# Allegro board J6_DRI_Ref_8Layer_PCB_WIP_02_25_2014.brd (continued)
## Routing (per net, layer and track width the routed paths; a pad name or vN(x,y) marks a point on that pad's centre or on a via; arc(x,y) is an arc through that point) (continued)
H_DDR2_RASN: length 80.5
  TOP w0.102: v1(66.37,51.64) U52.T23
  TOP w0.127: U68.F3 79.83,26.98 79.96,27.1 80.11,27.1 80.57,27.56 TP2MA2.1 ; R286.1 v2(104.29,28.4) ; TP2MB2.1 94.92,27.56 94.46,27.1 94.31,27.1 94.18,26.98 U69.F3
  L3-SIGNAL w0.114: v2(65.68,36.78) 66.19,37.29 66.19,37.69 66.29,37.79 66.65,37.79 66.75,37.89 66.75,38.09 66.65,38.2 66.29,38.2 66.19,38.3 66.19,38.5 66.29,38.6 66.63,38.6 66.75,38.72 66.75,38.89 66.63,39.01 66.29,39.01 66.19,39.11 66.19,39.31 66.29,39.41 66.65,39.41 66.75,39.52 66.75,39.72 66.65,39.82 66.29,39.82 66.19,39.92 66.19,40.13 66.29,40.23 66.65,40.23 66.75,40.33 66.75,40.53 66.65,40.63 66.29,40.63 66.19,40.74 66.19,40.94 66.29,41.04 66.65,41.04 66.75,41.14 66.75,41.35 66.65,41.45 66.29,41.45 66.19,41.55 66.19,41.75 66.29,41.85 66.72,41.85 66.84,41.97 66.84,42.14 66.72,42.26 66.29,42.26 66.19,42.36 66.19,44.29 66.43,44.53 66.43,44.88 66.19,45.13 66.19,46.04 66.29,46.14 66.56,46.14 66.68,46.26 66.68,46.43 66.56,46.55 66.29,46.55 66.19,46.65 66.19,46.89 66.31,47.01 66.51,47.01 66.62,47.12 66.62,47.35 66.51,47.46 66.31,47.46 66.19,47.58 66.19,48.16 66.85,48.82 66.85,51.18 v1(66.37,51.64)
  L6-SIGNAL w0.102: v2(104.29,28.4) 103.43,28.4 103.28,28.55 102.52,28.55 102.3,28.33 102.3,27.96 102.03,27.69 100.91,27.69 100.46,27.23 99.85,27.23 99.59,27.49 97.38,27.49 96.77,28.09 96.29,28.09 TP2MB2.1 93.22,27.56 93.14,27.49 91.65,27.49 91.12,28.02 90.04,28.02 89.79,28.27 85.7,28.27 85.19,27.76 84.08,27.76 83.8,27.49 82.93,27.49 82.5,27.92 81.76,27.92 TP2MA2.1 79.17,27.56 78.99,27.38 78.26,27.38 78.13,27.51 77.5,27.51 75.08,29.92 75.08,30.56 71.78,33.86 70.51,33.86 68.35,36.02 68.35,36.16 68.74,36.55 68.74,36.72 68.62,36.84 68.45,36.84 68.06,36.45 67.92,36.45 67.59,36.78 v2(65.68,36.78)
  BOTTOM w0.127: TP2MB2.1 96.16,27.97 96.72,27.97 97.03,27.66 97.03,27.25 97.38,26.9 U115.F3 ; TP2MA2.1 81.81,27.97 82.37,27.97 82.68,27.66 82.68,27.25 83.03,26.9 U116.F3
H_DDR2_RST: length 74
  TOP w0.102: U52.R24 v1(66.36,50.84)
  TOP w0.127: U68.N2 79.03,20.49 79.4,20.12 v2(79.4,19.26) ; v2(93.75,19.26) 93.75,20.69 U69.N2
  L3-SIGNAL w0.102: v2(93.75,19.26) 92.22,19.26 91.87,18.91
  L3-SIGNAL w0.114: 91.87,18.91 81.38,18.91 80.64,19.64 79.79,19.64 v2(79.4,19.26) 79.07,18.93 72.87,18.93 v2(70.26,21.54)
  BOTTOM w0.102: v1(66.36,50.84) 66.36,50.31 66.56,50.11 66.56,49.04
  BOTTOM w0.127: v2(79.4,19.26) 79.79,18.86 82.69,18.86 83.31,19.48 83.31,20.54 U116.N2 ; U115.N2 97.66,20.54 97.66,19.48 97.04,18.86 94.15,18.86 v2(93.75,19.26) ; v2(70.26,21.54) 69.24,22.56 69.24,25 69.63,25.39 69.63,29.15 69.8,29.31 69.8,30.89 69.24,31.45 69.24,34.24 68.1,35.38 68.1,36.78 66.83,38.05 66.83,39.96 65.84,40.95 65.84,44.17 66.07,44.4 66.07,47.2 66.19,47.32 66.19,48.67 66.56,49.04
H_DDR2_WEN: length 77.9
  TOP w0.102: v1(65.63,49.82) U52.U25
  TOP w0.127: RN3.4 v1(104.3,25.93) ; U68.H3 80.28,25.06 80.61,25.39 81.33,25.39 TP2MA9.1 ; U69.H3 94.63,25.06 94.97,25.4 95.67,25.4 TP2MB9.1
  L3-SIGNAL w0.114: v2(65.18,35.13) 66.19,34.11 69.29,34.11 69.55,33.86 70.56,33.86 70.82,34.11 71.4,34.11 71.5,34.01 71.5,33.47 71.62,33.35 71.79,33.35 71.91,33.47 71.91,34.01 72.01,34.11 72.21,34.11 72.31,34.01 72.31,33.47 72.43,33.35 72.6,33.35 72.72,33.47 72.72,34.01 72.82,34.11 73.02,34.11 73.13,34.01 73.13,33.47 73.25,33.35 73.41,33.35 73.53,33.47 73.53,33.86 73.66,33.99 73.99,33.99 74.12,33.86 74.12,33 73.76,32.64 73.76,31.57 73.86,31.47 73.86,27.84 75.84,25.86 79.02,25.86 79.45,25.43 81.29,25.43 TP2MA9.1
  L6-SIGNAL w0.102: v1(104.3,25.93) 104.3,25.33 103.93,24.96 103.39,24.96 103.28,25.08 102.15,25.08 101.93,25.3 99.39,25.3 99.16,25.08 98.14,25.08 98.04,25.17 96.29,25.17 96.11,25.35 TP2MB9.1 94.89,25.35 94.59,25.05 94.39,25.05 94.26,25.17 94.26,25.35 94.13,25.48 93.57,25.48 93.45,25.35 93.45,25.17 93.32,25.05 92.71,25.05 92.38,25.38 84.89,25.38 84.58,25.07 83.87,25.07 83.74,25.2 83.74,25.35 83.62,25.48 83.26,25.48 82.96,25.17 81.89,25.17 TP2MA9.1
  BOTTOM w0.102: 65.31,48.88 65.21,48.99 65.21,49.49 65.36,49.64 v1(65.63,49.82) ; U116.H3 82.79,25.06 82.5,25.35 TP2MA9.1 ; U115.H3 97.14,25.06 96.85,25.35 TP2MB9.1
  BOTTOM w0.127: v2(65.18,35.13) 65.68,35.64 65.68,36.15 65.18,36.65 65.18,39.5 64.8,39.88 64.8,44.88 65.19,45.27 65.19,47.73 65.31,47.85 65.31,48.88
H_EMU0: length 0.5
  TOP w0.102: v1(72.75,53.27) U52.G21
H_EMU1: length 1.1
  TOP w0.102: U52.D24 75.53,50.4 v1(75.72,50.22)
H_GPIO5_18: length 10.1
  TOP w0.102: U52.V2 64.27,68.86 64,69.13 64,70.92
  TOP w0.127: 64.21,78.56 64.21,74.4 63.83,74.02 63.83,71.58 64,71.41 64,70.92
H_GPIO5_19: length 0.7
  TOP w0.102: v1(62.74,70.31) 62.73,70.3 U52.Y1
H_GPIO6_10: length 0.6
  TOP w0.102: U52.AC5 v1(59.94,66.86)
H_GPIO6_11: length 0.6
  TOP w0.102: 61.13,67.26 v1(60.73,67.64)
H_GPIO6_16: length 0.5
  TOP w0.102: v1(73.58,53.25) U52.F21
H_GPIO6_28: length 0.6
  TOP w0.102: U52.Y9 v1(62.33,63.68)
H_GPIO7_7: length 0.6
  TOP w0.102: U52.A25 v1(78.33,50.04)
H_GPIO7_8: length 0.6
  TOP w0.102: v1(74.33,58.05) U52.F16
H_GPIO7_9: length 0.6
  TOP w0.102: U52.B25 v1(77.53,50.04)
H_GPIO7_10: length 12.2
  TOP w0.102: 79.2,51.25 U52.A24
  TOP w0.127: 79.2,51.25 79.59,51.25 79.96,50.88 89.99,50.88
H_GPIO7_11: length 12.4
  TOP w0.102: U52.A22 78.11,52.68 79.04,52.68 79.2,52.53
  TOP w0.127: 79.2,52.53 80.34,51.39 89.74,51.39
H_GPMC_A1: length 0.6
  TOP w0.102: U52.T9 v1(65.53,63.7)
H_GPMC_A2: length 0.6
  TOP w0.102: v1(65.49,66.06) U52.T6
H_GPMC_A3: length 0.6
  TOP w0.102: v1(66.33,64.46) U52.T7
H_GPMC_A4: length 0.5
  TOP w0.102: U52.P6 v1(67.94,65.3)
H_GPMC_A5: length 0.6
  TOP w0.102: v1(67.13,63.65) U52.R9
H_GPMC_A6: length 0.6
  TOP w0.102: v1(66.34,66.01) U52.R5
H_GPMC_A7: length 0.6
  TOP w0.102: U52.P5 v1(67.98,66.86)
H_GPMC_A8: length 0.6
  TOP w0.102: v1(67.91,64.46) U52.N7
H_GPMC_A9: length 0.8
  TOP w0.102: U52.R4 v1(66.23,67.89)
H_GPMC_A10: length 0.5
  TOP w0.102: U52.N9 v1(67.97,63.65)
H_GPMC_A11: length 0.6
  TOP w0.102: v1(67.13,62.87) U52.P9
H_GPMC_A12: length 0.7
  TOP w0.102: U52.P4 67.67,67.4 v1(68.09,67.76)
H_GPMC_ADV_N: length 9.1
  TOP w0.102: 68.33,70.92 U52.N1
  TOP w0.127: 68.33,70.92 68.33,71.26 68.47,71.39 68.47,74.08 69.04,74.65 69.04,78.44
H_GPMC_BEN0: length 0.5
  TOP w0.102: U52.N6 67.99,66.04 67.98,66.05 v1(67.98,66.05)
H_GPMC_BEN1: length 0.8
  TOP w0.102: v1(68.63,67.89) U52.M4
H_GPMC_CLK: length 0.6
  TOP w0.102: U52.P7 v1(67.11,64.47)
H_GPMC_CS0_N: length 9.2
  TOP w0.102: 65.93,70.92 U52.T1
  TOP w0.127: 65.93,70.92 65.93,70.92 65.93,74.18 66.62,74.88 66.62,78.56
H_GPMC_CS1_N: length 0.5
  TOP w0.102: U52.H6 v1(72.74,65.3)
H_GPMC_CS2_N: length 10.3
  TOP w0.102: 67.13,70.92 67.13,69.42 67.53,69.02 U52.P2
  TOP w0.127: 67.13,70.92 67.13,71.46 67.7,72.03 67.7,73.92 67.13,74.49 67.13,78.51
H_GPMC_CS3_N: length 9.2
  TOP w0.102: 67.53,70.92 U52.P1
  TOP w0.127: 68.53,78.44 68.53,74.86 67.96,74.29 67.96,71.9 67.53,71.47 67.53,70.92
H_GPMC_D00: length 0.6
  TOP w0.102: U52.M6 v1(68.74,65.26)
H_GPMC_D01: length 9.9
  TOP w0.102: U52.M2 69.13,69.07 68.78,69.42 68.78,70.92
  TOP w0.127: 69.29,78.44 69.29,74.55 68.81,74.06 68.81,70.94 68.78,70.92
H_GPMC_D02: length 0.6
  TOP w0.102: v1(70.38,66.86) U52.L5
H_GPMC_D03: length 9.1
  TOP w0.102: U52.M1 69.13,70.92
  TOP w0.127: 69.13,70.92 69.13,71.3 69.74,71.9 69.74,74.31 69.55,74.5 69.55,78.44
H_GPMC_D04: length 0.5
  TOP w0.102: v1(70.34,65.3) U52.L6
H_GPMC_D05: length 0.7
  TOP w0.102: v1(70.49,67.76) U52.L4
H_GPMC_D06: length 0.7
  TOP w0.102: U52.L3 v1(70.52,68.37)
H_GPMC_D07: length 10.5
  TOP w0.102: 69.55,70.92 69.55,69.29 69.93,68.91 U52.L2
  TOP w0.127: 69.55,70.92 69.55,70.95 70.62,72.03 70.62,73.92 70.43,74.11 70.43,74.12 69.8,74.75 69.8,78.44
H_GPMC_D08: length 9.6
  TOP w0.102: U52.L1 69.93,70.92
  TOP w0.127: 69.93,70.92 69.93,70.98 70.88,71.93 70.88,74.06 70.05,74.88 70.05,78.56
H_GPMC_D09: length 10.4
  TOP w0.102: U52.K2 70.73,68.87 70.31,69.29 70.31,70.92
  TOP w0.127: 70.31,70.92 70.31,70.99 71.13,71.82 71.13,74.18 70.31,75.01 70.31,78.44
H_GPMC_D10: length 9.1
  TOP w0.102: 71.53,70.92 U52.J1
  TOP w0.127: 71.53,70.92 71.53,71.41 71.7,71.58 71.7,73.87 72.21,74.37 72.21,78.44
H_GPMC_D11: length 10
  TOP w0.102: U52.J2 71.53,68.96 71.2,69.29 71.2,70.92
  TOP w0.127: 71.96,78.44 71.96,74.5 71.45,73.99 71.45,71.71 71.2,71.45 71.2,70.92
H_GPMC_D12: length 9.5
  TOP w0.102: U52.H1 72.33,70.69 72.56,70.92
  TOP w0.127: 73.99,78.44 73.99,74.75 73.67,74.44 73.67,72.03 72.56,70.92
H_GPMC_D13: length 0.6
  TOP w0.102: v1(71.07,68.45) U52.J3
H_GPMC_D14: length 10.2
  TOP w0.102: U52.H2 72.33,68.92 71.96,69.29 71.96,70.92
  TOP w0.127: 71.96,70.92 71.96,70.97 72.77,71.78 72.77,74.07 72.47,74.37 72.47,78.44
H_GPMC_D15: length 0.7
  TOP w0.102: v1(72.92,68.37) U52.H3
H_GPMC_OE_N: length 0.6
  TOP w0.102: v1(68.71,66.03) U52.M5
H_GPMC_WAIT0: length 10.1
  TOP w0.102: 67.89,70.92 67.89,69.29 68.33,68.86 U52.N2
  TOP w0.127: 67.89,70.92 67.89,71.33 68.21,71.64 68.21,74.19 68.78,74.76 68.78,78.44
H_GPMC_WE_N: length 0.6
  TOP w0.102: v1(68.67,68.45) U52.M3
H_HDMI_TX0+: length 7.9
  TOP w0.089: 48.58,56.5 54.5,56.5 54.91,56.92 56.26,56.92 U52.AH17
H_HDMI_TX0-: length 8.9
  TOP w0.089: U52.AG17 56.79,56.85 56.45,57.19 54.8,57.19 54.38,56.77 48.58,56.77
H_HDMI_TX1+: length 8.1
  TOP w0.089: 48.42,55.74 54.77,55.74 55.16,56.12 56.26,56.12 U52.AH18
H_HDMI_TX1-: length 8.9
  TOP w0.089: U52.AG18 56.79,56.39 55.05,56.39 54.66,56.01 48.53,56.01
H_HDMI_TX2+: length 8.4
  TOP w0.089: 48.1,55.06 55.41,55.06 55.67,55.32 56.26,55.32 U52.AH19
H_HDMI_TX2-: length 9
  TOP w0.089: U52.AG19 56.79,55.59 55.56,55.59 55.3,55.32 48.37,55.32
H_HDMI_TXC+: length 7.9
  TOP w0.089: 48.67,57.32 54.17,57.32 54.57,57.72 56.26,57.72 U52.AH16
H_HDMI_TXC-: length 8.7
  TOP w0.089: U52.AG16 56.79,57.99 54.46,57.99 54.05,57.58 48.78,57.58
H_I2C1_SCL: length 1.3
  TOP w0.102: U52.C21 v1(76.65,53.07) ; v1(76.73,54.9) U52.C20
H_I2C2_SCL: length 1.2
  TOP w0.102: v1(76.76,50.02) U52.C25 ; U52.F17 v1(73.54,57.25)
H_I2C3_SCL: length 0.5
  TOP w0.102: U52.F20 v1(73.54,54.82)
H_I2C3_SDA: length 0.6
  TOP w0.102: v1(75.14,53.2) U52.E21
H_JTAG_RTCK: length 0.6
  TOP w0.102: v1(75.2,55.67) 75.16,55.71 75.03,55.72 U52.E18
H_JTAG_TCK: length 0.5
  TOP w0.102: v1(74.35,54.79) U52.E20
H_JTAG_TDI: length 0.8
  TOP w0.102: U52.D23 v1(76.16,52.55)
H_JTAG_TDO: length 0.6
  TOP w0.102: U52.F19 74.29,55.55 v1(74.36,55.63)
H_JTAG_TMS: length 0.6
  TOP w0.102: v1(74.35,56.44) U52.F18
H_JTAG_TRST_N: length 0.8
  TOP w0.102: v1(76.16,54.95) U52.D20
H_LJCB_CLKN: length 11.7
  TOP w0.102: U52.AH15 53.8,58.45
  TOP w0.127: 45.06,59.31 45.95,59.31 46.38,58.88 51.97,58.88 52.4,58.45 53.09,58.45 53.21,58.33 53.58,58.33 53.69,58.45 53.8,58.45
H_MCASP1_ACLKR: length 18.4
  TOP w0.102: 79.2,59.77 78.56,59.77 78.49,59.69 77.6,59.69 77.16,59.26 U52.B14
  TOP w0.127: 95,59.96 86.62,59.96 86.11,59.45 82.52,59.45 82.21,59.77 79.2,59.77
H_MCASP1_ACLKX: length 0.6
  TOP w0.102: v1(76.73,59.72) U52.C14
H_MCASP1_AXR0: length 0.6
  TOP w0.102: v1(72.73,60.48) U52.G12
H_MCASP1_AXR1: length 0.5
  TOP w0.102: v1(73.58,60.45) U52.F12
H_MCASP1_AXR2: length 0.6
  TOP w0.102: v1(72.73,59.66) U52.G13
H_MCASP1_AXR3: length 0.6
  TOP w0.102: U52.J11 v1(71.93,62.06)
H_MCASP1_AXR4: length 0.6
  TOP w0.102: v1(75.13,60.4) 75.13,60.41 U52.E12
H_MCASP1_AXR5: length 0.6
  TOP w0.102: v1(74.33,60.5) U52.F13
H_MCASP1_AXR6: length 0.7
  TOP w0.102: U52.C12 v1(76.65,60.27)
H_MCASP1_AXR7: length 0.7
  TOP w0.102: U52.D12 v1(76.04,60.3)
H_MCASP1_AXR8: length 19.2
  TOP w0.102: U52.B12 77.13,61.01 77.42,61.29 79.2,61.29
  TOP w0.127: 79.2,61.29 79.6,61.29 80.21,60.68 81.94,60.68 82.23,60.98 84.29,60.98 85.06,60.21 85.79,60.21 87.05,61.47 94.87,61.47
H_MCASP1_AXR9: length 16.4
  TOP w0.102: 79.2,61.66 U52.A11
  TOP w0.127: 93.76,61.74 86.75,61.74 86.25,61.23 82.05,61.23 81.84,61.01 80.37,61.01 79.72,61.66 79.2,61.66
H_MCASP1_AXR10: length 18.9
  TOP w0.102: U52.B13 77.13,60.12 77.42,60.4 79.2,60.4
  TOP w0.127: 79.2,60.4 82.05,60.4 82.37,60.72 84.19,60.72 84.95,59.96 85.9,59.96 87.16,61.22 94.92,61.22
H_MCASP1_AXR11: length 0.7
  TOP w0.102: U52.A12 v1(78.61,60.78)
H_MCASP1_AXR12: length 0.6
  TOP w0.102: v1(74.29,59.65) U52.E14
H_MCASP1_AXR13: length 17.5
  TOP w0.102: 79.2,60.06 U52.A13
  TOP w0.127: 95.11,60.21 86.51,60.21 86.01,59.71 82.65,59.71 82.3,60.06 79.2,60.06
H_MCASP1_AXR14: length 0.6
  TOP w0.102: U52.G14 v1(73.54,59.65)
H_MCASP1_AXR15: length 21.7
  TOP w0.102: 79.2,58.75 78.47,58.75 78.38,58.84 74.29,58.84 73.93,59.19 U52.F14
  TOP w0.127: 79.2,58.75 79.4,58.75 80.04,59.39 82.16,59.39 82.35,59.2 86.22,59.2 86.72,59.71 94.82,59.71
H_MCASP1_FSR: length 0.5
  TOP w0.102: U52.J14 v1(71.89,59.65)
H_MCASP1_FSX: length 0.8
  TOP w0.102: U52.D14 v1(76.16,59.76)
H_MCASP2_ACLKR: length 0.6
  TOP w0.102: v1(75.14,58) U52.E15
H_MCASP2_ACLKX: length 0.6
  TOP w0.102: v1(78.32,55.65) U52.A19
H_MCASP2_AXR0: length 18.5
  TOP w0.102: 79.2,58.12 77.47,58.12 U52.B15
  TOP w0.127: 79.2,58.12 79.55,58.12 80.31,58.88 81.84,58.88 82.04,58.68 82.04,58.14 82.58,57.61 94.39,57.61
H_MCASP2_AXR1: length 17.6
  TOP w0.102: 79.2,58.45 U52.A15
  TOP w0.127: 79.2,58.45 79.48,58.45 80.16,59.13 81.98,59.13 82.17,58.94 83.27,58.94 84.35,57.86 94.74,57.86
H_MCASP2_AXR2: length 0.7
  TOP w0.102: U52.C15 v1(76.65,57.87)
H_MCASP2_AXR3: length 17.4
  TOP w0.102: 79.2,57.23 78.77,57.65 U52.A16
  TOP w0.127: 94.59,55.93 84.35,55.93 83.92,56.37 80.06,56.37 79.2,57.23
H_MCASP2_AXR4: length 0.7
  TOP w0.102: v1(76.04,57.9) U52.D15
H_MCASP2_AXR5: length 0.6
  TOP w0.102: v1(77.52,57.25) U52.B16
H_MCASP2_AXR6: length 0.5
  TOP w0.102: U52.B17 v1(77.52,56.47)
H_MCASP2_AXR7: length 0.6
  TOP w0.102: v1(78.32,57.25) U52.A17
H_MCASP2_FSR: length 11.8
  TOP w0.102: 79.2,55.45 78.93,55.45 U52.A20
  TOP w0.127: 89.36,55.45 79.2,55.45
H_MCASP2_FSX: length 0.6
  TOP w0.102: v1(78.32,56.45) U52.A18
H_MCASP3_ACLKX: length 0.6
  TOP w0.102: U52.B18 v1(77.53,55.65)
H_MCASP3_AFSX: length 0.5
  TOP w0.102: v1(73.58,58.05) U52.F15
H_MCASP3_AXR0: length 0.5
  TOP w0.102: U52.B19 v1(77.52,54.87)
H_MCASP3_AXR1: length 0.6
  TOP w0.102: v1(76.73,57.31) U52.C17
H_MCASP4_ACLKX: length 0.7
  TOP w0.102: U52.C18 v1(76.65,55.47)
H_MCASP4_AFSX: length 12.1
  TOP w0.102: 79.2,54.66 78.19,53.65 U52.A21
  TOP w0.127: 89.48,54.94 79.48,54.94 79.2,54.66
H_MCASP4_AXR0: length 0.5
  TOP w0.102: v1(72.75,58.04) U52.G16
H_MCASP4_AXR1: length 0.8
  TOP w0.102: v1(76.16,57.35) U52.D17
H_MCASP5_ACLKX: length 0.5
  TOP w0.102: v1(61.58,68.45) U52.AA3
H_MCASP5_AFSX: length 0.6
  TOP w0.102: 61.13,63.26 v1(61.53,62.87)
H_MCASP5_AXR0: length 0.6
  TOP w0.102: v1(61.49,67.64) 61.13,68.06
H_MCASP5_AXR1: length 0.6
  TOP w0.102: v1(61.51,66.89) U52.AA4
H_MDIO_D: length 0.7
  TOP w0.102: v1(65.68,67.76) U52.U4
H_MDIO_MCLK: length 9.2
  TOP w0.102: 64.33,70.92 U52.V1
  TOP w0.127: 64.33,70.92 64.33,71.32 64.78,71.77 64.78,74.06 64.47,74.37 64.47,78.56
H_MLBP_CLK_N: length 12.8
  TOP w0.089: 61.13,68.86 60.76,69.22 60.76,69.75 60.77,69.75 60.77,71.6 59.64,72.73 59.64,75.51 59.66,75.53 59.61,75.58 59.61,76.22 59.99,76.59 60.13,76.59 60.13,80.72
H_MLBP_CLK_P: length 12.1
  TOP w0.089: 60.4,80.72 60.4,76.32 60.1,76.32 59.85,76.07 59.85,75.72 60.04,75.53 59.91,75.4 59.91,72.84 61.04,71.71 61.04,69.75 61.13,69.66
H_MLBP_DAT_N: length 11.9
  TOP w0.089: U52.AA2 61.56,69.22 61.56,69.74 61.57,69.75 61.57,71.02 62.17,71.61 62.17,80.39
H_MLBP_DAT_P: length 11
  TOP w0.089: 62.43,80.39 62.43,71.5 61.84,70.91 61.84,69.75 U52.AA1
H_MLBP_SIG_N: length 14.7
  TOP w0.089: U52.AC2 59.9,69.28 59.9,71.34 58.86,72.38 58.86,75.95 58.86,75.95 58.86,76.3 58.5,76.66 58.5,78.14 59.35,78.99 59.35,81.52 58.71,82.16
H_MLBP_SIG_P: length 13.7
  TOP w0.089: U52.AC1 60.17,69.82 60.17,71.45 59.13,72.49 59.13,76.06 59.29,76.22 59.29,76.31 59.62,76.64 59.62,81.63 58.9,82.35
H_MMC1_CLK: length 0.6
  TOP w0.102: v1(63.12,66.06) U52.W6
H_MMC1_CMD: length 0.6
  TOP w0.102: v1(63.14,65.26) U52.Y6
H_MMC1_DAT0: length 0.5
  TOP w0.102: U52.AA6 v1(62.32,66.03)
H_MMC1_DAT1: length 0.7
  TOP w0.102: v1(63.28,67.76) U52.Y4
H_MMC1_DAT2: length 0.6
  TOP w0.102: v1(61.49,66.07) U52.AA5
H_MMC1_DAT3: length 0.7
  TOP w0.102: U52.Y3 v1(63.31,68.37)
H_MMC1_SD_CD: length 0.6
  TOP w0.102: v1(63.14,64.46) U52.W7
H_MMC2_CLK: length 0.5
  TOP w0.102: U52.J7 v1(71.16,64.46)
H_MMC2_DAT0: length 0.8
  TOP w0.102: v1(71.03,67.89) U52.J4
H_MMC2_DAT1: length 0.6
  TOP w0.102: U52.J6 v1(71.14,65.26)
H_MMC2_DAT2: length 0.7
  TOP w0.102: v1(72.89,67.76) U52.H4
H_MMC2_DAT3: length 0.6
  TOP w0.102: v1(72.78,66.86) U52.H5
H_MMC2_DAT4: length 0.6
  TOP w0.102: v1(70.35,64.46) U52.K7
H_MMC2_DAT5: length 0.6
  TOP w0.102: U52.M7 v1(68.73,64.46)
H_MMC2_DAT6: length 0.6
  TOP w0.102: v1(71.14,66.06) 71.14,66.01 U52.J5
H_MMC2_DAT7: length 0.5
  TOP w0.102: U52.K6 70.43,66.01 v1(70.38,66.06)
H_MMC3_CLK: length 0.5
  TOP w0.102: U52.AD4 v1(59.18,67.66)
H_MMC3_CMD: length 0.5
  TOP w0.102: U52.AC4 v1(59.95,67.64)
H_MMC3_DAT0: length 0.6
  TOP w0.102: v1(59.93,64.42) U52.AC7
H_MMC3_DAT1: length 0.6
  TOP w0.102: U52.AC6 v1(60.72,65.26)
H_MMC3_DAT2: length 0.6
  TOP w0.102: U52.AC9 v1(60.73,62.86)
H_MMC3_DAT3: length 0.5
  TOP w0.102: v1(59.93,68.42) 60.28,68.11 U52.AC3
H_MMC3_DAT4: length 0.6
  TOP w0.102: v1(60.71,64.46) U52.AC8
H_MMC3_DAT5: length 0.6
  TOP w0.102: v1(59.92,65.26) U52.AD6
H_MMC3_DAT6: length 0.6
  TOP w0.102: 61.13,64.06 v1(61.53,64.47)
H_MMC3_DAT7: length 0.6
  TOP w0.102: v1(60.71,66.85) 61.13,66.46
H_MMC4_CLK: length 0.5
  TOP w0.102: v1(75.09,50.05) U52.E25
H_MMC4_CMD: length 0.6
  TOP w0.102: U52.C27 v1(76.73,48.44)
H_MMC4_DAT0: length 4.6
  TOP w0.127: 75.53,48.05 76.34,47.25 76.94,47.25 77.24,47.55 78.82,47.55 v2(79.4,48.14)
H_MMC4_DAT1: length 0.6
  TOP w0.102: v1(75.92,49.25) U52.D26
H_MMC4_DAT2: length 0.6
  TOP w0.102: U52.D27 v1(75.93,48.44)
H_MMC4_DAT3: length 0.6
  TOP w0.102: 76.33,48.05 v1(76.73,47.64)
H_NMIN: length 0.7
  TOP w0.102: U52.D21 v1(76.04,53.1)
H_ON_OFF: length 0.5
  TOP w0.102: v1(62.34,61.27) U52.Y11
H_OSC0_RTN: length 0.7
  TOP w0.102: v1(57.71,57.74) U52.AF15
H_OSC0_XIN: length 6.5
  TOP w0.089: C128.1 40.53,56.15 40.53,56.88 40.87,57.22 42.41,57.22 42.49,57.13 Y6.1 ; v1(58.29,58.02) U52.AE15
H_OSC0_XOUT: length 6.4
  TOP w0.089: C126.1 40.87,58.22 40.87,57.58 40.96,57.49 42.41,57.49 42.49,57.58 Y6.2 ; v1(59.14,58.03) U52.AD15
H_OSC1_RTN: length 0.5
  TOP w0.089: U52.AC14 v1(60.68,59.66)
H_OSC1_XIN: length 0.6
  TOP w0.102: v1(59.94,58.04) U52.AC15
H_OSC1_XOUT: length 0.6
  TOP w0.089: U52.AC13 v1(59.94,59.66)
H_OSCRTC_XIN: length 0.7
  TOP w0.089: U52.AE14 v1(58.23,59.81)
H_OSCRTC_XOUT: length 0.6
  TOP w0.089: v1(59.13,59.66) U52.AD14
H_PCIE_RXN0: length 1.5
  TOP w0.102: U52.AG13 57.13,60.07 56.74,60.45 56.24,60.45 56.21,60.48 v1(55.83,60.48)
H_PCIE_RXN1: length 12.5
  TOP w0.102: 53.8,63.71 53.91,63.71 54.5,63.12 54.5,62.38 54.83,62.05 56.72,62.05 57.12,61.66 U52.AG11
  TOP w0.127: 45.87,63.71 53.8,63.71
H_PCIE_RXP0: length 11.6
  TOP w0.102: 53.8,60.91 54.13,60.58 54.13,60.43 54.5,60.06 U52.AH13
  TOP w0.127: 53.8,60.91 53.62,61.09 45.24,61.09
H_PCIE_RXP1: length 11.9
  TOP w0.102: U52.AH11 54.86,61.66 54.29,62.22 54.29,63.04 53.88,63.45 53.8,63.45
  TOP w0.127: 45.67,63.45 53.8,63.45
H_PCIE_TXN0: length 12.6
  TOP w0.102: U52.AG14 56.98,59.26 56.59,59.64 54.48,59.64 54.23,59.9 53.8,59.9
  TOP w0.127: 45.24,60.84 51.55,60.84 52.02,60.36 52.02,60.23 52.35,59.9 53.8,59.9
H_PCIE_TXN1: length 2.3
  TOP w0.102: U52.AG12 57.13,60.88 56.72,61.29 55.04,61.29
H_PCIE_TXP0: length 11.9
  TOP w0.102: U52.AH14 54.39,59.26 54.05,59.59 53.8,59.59
  TOP w0.127: 45.11,60.58 51.31,60.58 51.74,60.15 51.74,59.84 51.99,59.59 53.8,59.59
H_PCIE_TXP1: length 0.3
  TOP w0.102: U52.AH12 55.99,60.86
H_POR_N: length 0.5
  TOP w0.178: v1(74.32,53.22) U52.F22
H_QSPI1_D0: length 9.2
  TOP w0.102: 65.13,70.92 U52.U1
  TOP w0.127: 65.13,70.92 65.13,71.23 65.35,71.45 65.35,74.25 64.97,74.63 64.97,78.56
H_QSPI1_D1: length 0.7
  TOP w0.102: v1(68.12,68.37) U52.P3
H_QSPI1_D2: length 10.2
  TOP w0.102: U52.U2 65.13,68.88 64.72,69.29 64.72,70.92
  TOP w0.127: 64.72,78.56 64.72,74.5 65.1,74.12 65.1,71.58 64.72,71.2 64.72,70.92
H_QSPI1_D3: length 10.1
  TOP w0.102: 65.48,70.92 65.48,69.29 65.92,68.86 U52.T2
  TOP w0.127: 65.23,78.56 65.23,74.75 65.61,74.37 65.61,71.33 65.48,71.2 65.48,70.92
H_QSPI1_RTCLK: length 0.6
  TOP w0.102: v1(66.27,68.45) U52.R3
H_QSPI1_SCLK: length 10.1
  TOP w0.102: U52.R2 66.73,68.93 66.35,69.31 66.35,70.92
  TOP w0.127: 66.88,78.56 66.88,74.63 66.83,74.58 66.83,71.78 66.35,71.31 66.35,70.92
H_RESET_N: length 0.6
  TOP w0.178: v1(74.33,52.45) U52.E23
H_RGMII0_RXC: length 0.6
  TOP w0.102: v1(65.58,66.86) U52.U5
H_RGMII0_RXCTL: length 0.6
  TOP w0.102: U52.V5 v1(63.94,66.01)
H_RGMII0_RXD0: length 10.1
  TOP w0.102: U52.W2 63.53,68.96 63.2,69.29 63.2,70.92
  TOP w0.127: 63.2,70.92 63.2,71.5 63.58,71.88 63.58,73.54 62.81,74.3 62.81,78.34
H_RGMII0_RXD1: length 0.6
  TOP w0.102: U52.Y2 62.73,68.87 v1(62.33,69.27)
H_RGMII0_RXD2: length 0.6
  TOP w0.102: v1(63.87,68.45) U52.V3
H_RGMII0_RXD3: length 0.8
  TOP w0.102: U52.V4 v1(63.83,67.89)
H_RGMII0_TD0: length 0.5
  TOP w0.102: U52.U6 v1(65.54,65.3)
H_RGMII0_TD1: length 0.6
  TOP w0.102: U52.V6 v1(63.94,65.26)
H_RGMII0_TD2: length 0.6
  TOP w0.102: v1(65.51,64.46) U52.U7
H_RGMII0_TD3: length 0.6
  TOP w0.102: U52.V7 v1(63.93,64.46)
H_RGMII0_TXC: length 0.6
  TOP w0.102: v1(63.17,62.84) U52.W9
H_RGMII0_TXCTL: length 0.6
  TOP w0.102: v1(63.93,63.68) U52.V9
H_RMII_50MHZ_CLK: length 0.7
  TOP w0.102: v1(65.71,68.37) U52.U3
H_RSTOUT_N: length 0.5
  TOP w0.102: v1(73.55,52.41) 73.57,52.41 U52.F23
H_RSV_Y5: length 0.6
  TOP w0.102: v1(63.15,66.86) U52.Y5
H_SATA1_TXN0: length 39.1
  TOP w0.102: 53.8,66.12 53.92,66.12 54.52,65.52 54.52,64.35 55.26,63.6 56.82,63.6 57.13,63.29 U52.AG9 ; U52.AG15 57.09,58.45 56.69,58.85 54.31,58.85 53.98,59.18 53.8,59.18 ; U52.AG10 57.13,62.53 56.85,62.82 55.42,62.82 54.11,64.12 54.11,65.35 53.85,65.61 53.8,65.61
  TOP w0.127: 45.14,59.62 45.19,59.67 46.48,59.67 46.96,59.18 53.17,59.18 53.21,59.22 53.58,59.22 53.61,59.18 53.8,59.18 ; 53.8,66.12 52.15,66.12 50.88,64.85 46.48,64.85 ; 46.2,64.34 51.09,64.34 52.36,65.61 53.8,65.61
H_SATA1_TXP0: length 23.1
  TOP w0.102: U52.AH9 55.27,63.26 54.32,64.21 54.32,65.43 53.89,65.86 53.8,65.86 ; 53.8,63.96 53.94,63.96 55.45,62.46 U52.AH10
  TOP w0.127: 53.8,65.86 52.26,65.86 50.99,64.59 46.58,64.59 ; 45.95,63.96 53.8,63.96
H_UART1_DBG_RX1: length 0.6
  TOP w0.102: U52.B27 v1(77.53,48.44)
H_UART1_DBG_TX1: length 0.6
  TOP w0.102: v1(76.73,49.25) U52.C26
H_UART3_CTS: length 0.5
  TOP w0.102: U52.G17 72.76,57.23 v1(72.75,57.23)
H_UART3_RTS: length 13.1
  TOP w0.102: 79.2,50.88 77.55,50.88 77.17,51.25 U52.B24
  TOP w0.127: 79.2,50.88 79.58,50.88 79.83,50.62 89.99,50.62
H_UART3_RXD: length 2.8
  TOP w0.102: 79.2,49.65 U52.A26
  TOP w0.127: 80.74,49.65 79.2,49.65
H_UART3_TXD: length 13.4
  TOP w0.102: 79.2,52.15 78.94,52.4 77.6,52.4 77.15,52.85 U52.B22
  TOP w0.127: 89.87,51.13 80.21,51.13 79.2,52.15
H_UART4_LIN_RXD: length 12.9
  TOP w0.102: 79.2,54.28 78.21,53.3 77.49,53.3 U52.B21
  TOP w0.127: 89.36,54.69 79.6,54.69 79.2,54.28
H_UART4_LIN_TXD: length 12.8
  TOP w0.102: U52.B20 77.15,54.45 77.48,54.12 78.11,54.12 79.18,55.2 79.2,55.2
  TOP w0.127: 89.36,55.2 79.2,55.2
H_USB1_DM: length 0.5
  TOP w0.102: U52.AC12 v1(60.68,60.45)
H_USB1_DP: length 0.6
  TOP w0.102: U52.AD12 v1(59.95,60.46)
H_USB1_DRV_VBUS: length 0.6
  TOP w0.178: 61.13,62.46 v1(60.68,62.06)
H_USB2_DM: length 0.7
  TOP w0.102: U52.AF11 v1(57.61,62.26)
H_USB2_DP: length 0.7
  TOP w0.102: U52.AE11 58.59,61.8 v1(58.23,62.21)
H_USB2_DRV_VBUS: length 0.6
  TOP w0.178: U52.AC10 v1(59.92,62.06)
H_VIN1A_CLK0: length 2.2
  TOP w0.102: U52.AG8 57.1,64.06 56.72,64.44 v2(55.12,64.44)
H_VIN1A_D0: length 0.7
  TOP w0.102: v1(58.23,64.61) U52.AE8
H_VIN1A_D1: length 0.6
  TOP w0.102: v1(59.13,64.51) U52.AD8
H_VIN1A_D2: length 0.6
  TOP w0.102: U52.AG7 57.13,64.87 v1(56.74,65.26)
H_VIN1A_D3: length 0.6
  TOP w0.102: U52.AH6 v1(55.78,65.66)
H_VIN1A_D4: length 11.9
  TOP w0.102: 53.8,70.49 54.23,70.49 55.22,69.5 55.22,68.72 55.88,68.06 U52.AH3
  TOP w0.127: 53.8,70.49 51.87,70.49 51.65,70.26 46.02,70.26
H_VIN1A_D5: length 9.5
  TOP w0.102: U52.AH5 55.75,66.46 54.19,68.02 53.8,68.02
  TOP w0.127: 47.45,68.02 53.8,68.02
H_VIN1A_D6: length 0.5
  TOP w0.102: U52.AG6 v1(56.74,66.04)
H_VIN1A_D7: length 9.5
  TOP w0.102: U52.AH4 55.53,67.26 54.25,68.53 53.8,68.53
  TOP w0.127: 47.4,68.53 53.8,68.53
H_VIN1A_D8: length 10.4
  TOP w0.102: 53.8,68.79 54.29,68.79 55.43,67.64 56.72,67.64 57.1,67.26 U52.AG4
  TOP w0.127: 47.37,68.79 53.8,68.79
H_VIN1A_D9: length 11.1
  TOP w0.102: 55.04,70.92 55.4,70.56 56.57,70.56 56.79,70.34 56.79,69.53 57.13,69.19 U52.AG2
  TOP w0.127: 48.11,72.24 53.72,72.24 55.04,70.92
H_VIN1A_D10: length 13
  TOP w0.102: 53.8,70.77 54.28,70.77 55.42,69.63 55.42,68.81 55.82,68.4 56.59,68.4 56.94,68.06 U52.AG3
  TOP w0.127: 45.82,70.51 51.54,70.51 51.79,70.77 53.8,70.77
H_VIN1A_D11: length 10.4
  TOP w0.102: 53.8,68.28 54.22,68.28 55.62,66.88 56.59,66.88 57.02,66.46 U52.AG5
  TOP w0.127: 53.8,68.28 47.45,68.28
H_VIN1A_D12: length 11.9
  TOP w0.102: 55.45,70.92 55.6,70.77 57.3,70.77 57.6,70.47 57.6,69.52 57.93,69.19 U52.AF2
  TOP w0.127: 55.45,70.92 53.85,72.52 48.29,72.52
H_VIN1A_D13: length 0.6
  TOP w0.102: v1(57.54,65.2) U52.AF6
H_VIN1A_D14: length 13.5
  TOP w0.102: U52.AF3 57.93,68.08 57.61,68.4 57.1,68.4 56.72,68.79 56.72,69.17 56.59,69.29 56.21,69.29 54.58,70.92
  TOP w0.127: 46,70.77 51.44,70.77 51.71,71.05 54.46,71.05 54.58,70.92
H_VIN1A_D15: length 0.6
  TOP w0.102: v1(57.52,67.65) U52.AF4
H_VIN1A_D16: length 10.9
  TOP w0.102: U52.AF1 57.93,70.48 57.49,70.92
  TOP w0.127: 48.77,72.77 54,72.77 55.77,71.01 57.4,71.01 57.49,70.92
H_VIN1A_D17: length 0.6
  TOP w0.102: v1(58.31,67.65) U52.AE3
H_VIN1A_D18: length 0.8
  TOP w0.102: v1(58.71,67.26) U52.AE5
H_VIN1A_D19: length 12.7
  TOP w0.102: U52.AE1 58.73,70.37 58.74,70.39 58.21,70.92
  TOP w0.127: 58.21,70.92 57.61,71.52 57.11,71.52 55.91,72.72 55.07,72.72 54.51,73.28 47.98,73.28
H_VIN1A_D20: length 13.3
  TOP w0.102: 57.85,70.92 58.37,70.4 58.37,69.29 58.73,68.93 U52.AE2
  TOP w0.127: 57.85,70.92 57.51,71.26 55.92,71.26 54.15,73.03 47.83,73.03
H_VIN1A_D21: length 0.8
  TOP w0.102: v1(58.1,65.15) U52.AE6
H_VIN1A_D22: length 14.6
  TOP w0.102: U52.AD2 59.53,68.89 59.13,69.29 59.13,70.92
  TOP w0.127: 48.18,73.71 55.88,73.71 56.85,72.75 57.68,72.75 59.13,71.3 59.13,70.92
H_VIN1A_D23: length 0.6
  TOP w0.102: U52.AD3 v1(59.08,68.46)
H_VIN1A_DE0: length 0.6
  TOP w0.102: v1(59.94,62.87) U52.AD9
H_VIN1A_FLD0: length 0.6
  TOP w0.102: v1(57.54,62.82) U52.AF9
H_VIN1A_HSYNC0: length 0.7
  TOP w0.102: v1(58.23,62.78) U52.AE9
H_VIN1A_VSYNC0: length 0.7
  TOP w0.102: v1(57.61,64.64) U52.AF8
H_VIN1B_CLK1: length 1.7
  TOP w0.102: v2(55,65.66) 55.8,64.86 U52.AH7
H_VIN2A_CLK0: length 11.9
  TOP w0.102: 75.03,70.92 74.73,70.63 U52.E1
  TOP w0.127: 79.2,79.3 79.2,74.32 78.59,73.71 77.82,73.71 75.03,70.92
H_VIN2A_D0: length 10.3
  TOP w0.102: U52.F2 73.93,69.19 73.54,69.58 73.54,70.72 73.74,70.92
  TOP w0.127: 73.74,70.92 74.55,71.73 74.55,74.14 74.8,74.4 74.8,78.46
H_VIN2A_D1: length 0.6
  TOP w0.102: U52.F3 v1(73.47,68.45)
H_VIN2A_D2: length 12
  TOP w0.102: U52.D1 75.53,70.71 75.75,70.92
  TOP w0.127: 75.75,70.92 78.03,73.21 78.81,73.21 79.71,74.11 79.71,79.48
H_VIN2A_D3: length 10
  TOP w0.102: U52.E2 74.37,69.22 74.37,70.92
  TOP w0.127: 74.37,70.92 74.37,71.19 74.82,71.64 74.82,74.01 75.08,74.27 75.08,78.41
H_VIN2A_D4: length 12.5
  TOP w0.102: U52.D2 75.13,69.26 75.13,70.66 75.39,70.92
  TOP w0.127: 75.39,70.92 77.93,73.46 78.7,73.46 79.45,74.21 79.45,78.92
H_VIN2A_D5: length 0.8
  TOP w0.102: v1(73.43,67.89) U52.F4
H_VIN2A_D6: length 11
  TOP w0.102: U52.C1 76.33,70.79 76.47,70.92
  TOP w0.127: 80.21,78.59 80.21,73.89 79.02,72.7 78.24,72.7 76.47,70.92
H_VIN2A_D7: length 0.8
  TOP w0.102: U52.E4 75.11,67.31 v1(75.53,67.28)
H_VIN2A_D8: length 0.6
  TOP w0.102: v1(73.54,66.01) U52.F5
H_VIN2A_D9: length 0.6
  TOP w0.102: v1(75.13,66.08) U52.E6
H_VIN2A_D10: length 0.6
  TOP w0.102: v1(75.93,68.46) U52.D3
H_VIN2A_D11: length 0.6
  TOP w0.102: U52.F6 v1(73.55,65.24)
H_VIN2A_D12: length 0.5
  TOP w0.102: v1(75.93,66.83) U52.D5
H_VIN2A_D13: length 12.8
  TOP w0.102: 76.11,70.92 75.95,70.76 75.95,69.25 U52.C2
  TOP w0.127: 79.96,79.35 79.96,74 78.91,72.95 78.14,72.95 76.11,70.92
H_VIN2A_D14: length 13
  TOP w0.102: U52.C3 76.78,68.51 76.78,70.74 76.83,70.79 76.83,70.92
  TOP w0.127: 85.06,75.01 83.29,73.23 80.05,73.23 78.89,72.06 77.98,72.06 76.83,70.92
H_VIN2A_D15: length 0.6
  TOP w0.102: U52.C4 v1(75.93,67.67)
H_VIN2A_D16: length 11.4
  TOP w0.102: 78.28,70.92 78.28,70.67 77.46,69.85 77.46,69.52 77.13,69.19 U52.B2
  TOP w0.127: 85.37,74.96 83.39,72.98 80.16,72.98 78.28,71.1 78.28,70.92
H_VIN2A_D17: length 0.5
  TOP w0.102: U52.D6 v1(75.91,66.04)
H_VIN2A_D18: length 0.6
  TOP w0.102: U52.C5 v1(76.74,66.91)
H_VIN2A_D19: length 11.8
  TOP w0.102: U52.A3 78.37,68.06 78.99,68.68 78.99,70.92
  TOP w0.127: 78.99,70.92 78.99,71.09 80.37,72.47 83.6,72.47 85.64,74.51
H_VIN2A_D20: length 12.2
  TOP w0.102: U52.B3 77.52,68.44 77.52,69.04 77.77,69.29 78.21,69.29 78.69,69.78 78.69,70.92
  TOP w0.127: 85.46,74.69 83.5,72.72 80.27,72.72 78.69,71.15 78.69,70.92
H_VIN2A_D21: length 14.3
  TOP w0.102: U52.B4 77.16,67.26 77.6,67.69 78.41,67.69 79.25,68.53
  TOP w0.127: 86.73,75.24 83.71,72.21 80.48,72.21 79.25,70.99 79.25,68.53
H_VIN2A_D22: length 13.7
  TOP w0.102: U52.B5 77.13,66.47 77.55,66.88 78.51,66.88 79.2,67.57
  TOP w0.127: 86.18,73.97 83.92,71.71 80.75,71.71 79.76,70.72 79.76,68.13 79.2,67.57
H_VIN2A_D23: length 12.3
  TOP w0.102: 79.2,68.12 79.19,68.12 78.33,67.26 U52.A4
  TOP w0.127: 79.2,68.12 79.5,68.43 79.5,70.88 80.58,71.96 83.81,71.96 85.99,74.14
H_VIN2A_DE0: length 10.4
  TOP w0.102: 72.92,70.92 72.72,70.72 72.72,69.17 73.03,68.86 U52.G2
  TOP w0.127: 72.92,70.92 73.93,71.92 73.93,74.31 74.24,74.63 74.24,78.44
H_VIN2A_FLD0: length 0.6
  TOP w0.102: U52.H7 v1(72.71,64.46)
H_VIN2A_HSYNC0: length 9.3
  TOP w0.102: 73.38,70.92 73.13,70.68 U52.G1
  TOP w0.127: 73.38,70.92 74.22,71.76 74.22,74.17 74.55,74.5 74.55,78.39
H_VIN2A_VSYNC0: length 0.6
  TOP w0.102: v1(72.69,66.06) U52.G6
H_VOUT1_CLK: length 0.8
  TOP w0.102: v1(76.16,62.16) U52.D11
H_VOUT1_D0: length 0.6
  TOP w0.102: U52.F11 v1(73.54,62.05)
H_VOUT1_D1: length 0.6
  TOP w0.102: v1(72.73,62.88) U52.G10
H_VOUT1_D2: length 0.6
  TOP w0.102: v1(74.33,62.88) U52.F10
H_VOUT1_D3: length 0.6
  TOP w0.102: U52.G11 v1(72.73,62.06)
H_VOUT1_D4: length 0.6
  TOP w0.102: v1(75.14,62.81) U52.E9
H_VOUT1_D5: length 0.6
  TOP w0.102: v1(73.51,62.87) U52.F9
H_VOUT1_D6: length 0.5
  TOP w0.102: v1(74.31,63.67) U52.F8
H_VOUT1_D7: length 0.6
  TOP w0.102: v1(75.13,65.3) U52.E7
H_VOUT1_D8: length 0.6
  TOP w0.102: v1(74.31,64.47) U52.E8
H_VOUT1_D9: length 0.7
  TOP w0.102: U52.D9 v1(76.04,62.7)
H_VOUT1_D10: length 0.6
  TOP w0.102: v1(75.91,65.26) U52.D7
H_VOUT1_D11: length 0.6
  TOP w0.102: v1(75.17,64.47) U52.D8
H_VOUT1_D12: length 13
  TOP w0.102: 79.2,66.96 78.7,66.46 U52.A5
  TOP w0.127: 86.31,73.74 84.02,71.45 80.9,71.45 80.06,70.61 80.06,67.82 79.2,66.96
H_VOUT1_D13: length 0.6
  TOP w0.102: v1(76.7,66.07) 76.39,65.71 U52.C6
H_VOUT1_D14: length 0.5
  TOP w0.102: v1(76.73,64.41) U52.C8
H_VOUT1_D15: length 0.6
  TOP w0.102: v1(75.92,64.49) U52.C7
H_VOUT1_D16: length 17.6
  TOP w0.102: 79.2,65.33 77.52,65.33 77.13,64.95 U52.B7
  TOP w0.127: 93.85,66.06 85.27,66.06 84.99,66.33 84.01,66.33 82.91,65.23 79.29,65.23 79.2,65.33
H_VOUT1_D17: length 18
  TOP w0.102: 79.2,64.72 79.04,64.72 78.85,64.53 77.6,64.53 U52.B8
  TOP w0.127: 94.51,65.55 85.16,65.55 84.33,64.72 79.2,64.72
H_VOUT1_D18: length 15.8
  TOP w0.102: 79.2,64.98 78.82,64.98 78.7,64.86 U52.A7
  TOP w0.127: 93.34,65.8 85.05,65.8 84.23,64.98 79.2,64.98
H_VOUT1_D19: length 15.8
  TOP w0.102: 79.2,64.21 79.04,64.06 U52.A8
  TOP w0.127: 93.48,64.66 84.75,64.66 84.56,64.47 79.45,64.47 79.2,64.21
H_VOUT1_D20: length 0.7
  TOP w0.102: U52.C9 v1(76.65,62.67)
H_VOUT1_D21: length 17.1
  TOP w0.102: 79.2,63.26 U52.A9
  TOP w0.127: 79.2,63.26 79.7,63.26 80.26,62.69 81.92,62.69 82.3,63.07 85.73,63.07 86.81,64.15 94.21,64.15
H_VOUT1_D22: length 18.1
  TOP w0.102: 79.2,63.71 77.55,63.71 77.13,63.29 U52.B9
  TOP w0.127: 79.2,63.71 79.32,63.58 82.44,63.58 82.7,63.32 84.64,63.32 85.72,64.4 94.37,64.4
H_VOUT1_D23: length 17.2
  TOP w0.102: U52.A10 79.2,62.46
  TOP w0.127: 79.2,62.46 79.53,62.46 79.81,62.18 82.21,62.18 82.59,62.56 84.47,62.56 85.3,61.74 86.03,61.74 87.18,62.88 94.07,62.88
H_VOUT1_DE: length 17.7
  TOP w0.102: 79.2,62.82 77.42,62.82 77.13,62.53 U52.B10
  TOP w0.127: 94.15,63.13 86.15,63.13 85.84,62.82 82.49,62.82 82.1,62.44 79.93,62.44 79.55,62.82 79.2,62.82
H_VOUT1_HSYNC: length 0.6
  TOP w0.102: v1(76.73,62.12) U52.C11
H_VOUT1_VSYNC: length 0.6
  TOP w0.102: v1(74.29,62.05) U52.E11
H_WAKEUP0: length 0.6
  TOP w0.102: v1(59.94,56.44) U52.AD17
H_WAKEUP2: length 0.6
  TOP w0.102: v1(60.73,58.05) 61.13,57.65
H_WAKEUP3: length 0.5
  TOP w0.102: v1(59.97,57.24) U52.AC16
H_XREF_CLK0: length 0.7
  TOP w0.102: v1(76.04,55.5) 75.67,55.91 U52.D18
H_XREF_CLK1: length 0.6
  TOP w0.102: v1(74.31,57.28) U52.E17
H_XREF_CLK2: length 0.6
  TOP w0.102: U52.B26 v1(77.53,49.24)
H_XREF_CLK3: length 0.6
  TOP w0.102: U52.C23 76.73,52.45 v1(76.73,52.51)
Net_418: length 0.6
  TOP w0.203: 130.78,82.22 131.18,82.62
Net_419: length 0.6
  TOP w0.102: 129.98,82.22 v1(130.38,82.62)
Net_420: length 0.6
  TOP w0.203: 129.98,81.42 130.38,81.82
Net_425: length 1.3
  TOP w0.254: v1(123.18,80.22) 123.58,79.82
  BOTTOM w0.254: 122.43,80.22 v1(123.18,80.22)
Net_1355: length 2.6
  TOP w0.102: 79.2,48.85 77.93,48.85
  TOP w0.127: 79.2,48.85 79.47,48.85 80.23,48.1
Net_1356: length 0.6
  TOP w0.102: v1(62.31,62.03) 62.73,62.45 62.73,62.46
Net_1357: length 0.6
  TOP w0.102: v1(59.16,62.08) 59.53,61.66
Net_1358: length 0.5
  TOP w0.102: v1(59.94,61.27) 60.33,61.66
Net_1359: length 0.8
  TOP w0.102: v1(58.1,60.35) 58.73,60.86
Net_1360: length 0.6
  TOP w0.102: v1(57.54,60.4) 57.93,60.86
PMIC_32K_CLKOUT: length 0.6
  TOP w0.102: v1(123.98,81.82) U45.M11
PMIC_BOOT0: length 4.6
  TOP w0.102: U45.L3 130.78,80.62 v1(131.18,80.22)
  BOTTOM w0.127: R518.1 134.06,81.23 133.68,81.23 132.92,80.47 132.58,80.47 132.33,80.72 131.69,80.72 v1(131.18,80.22)
PMIC_BOOT1: length 6.3
  TOP w0.102: v1(127.98,79.42) U45.K7
  BOTTOM w0.102: 127.98,80.36 127.98,80.45 127.58,80.85 127.58,82.88 127.84,83.14 127.84,83.44
  BOTTOM w0.127: v1(127.98,79.42) 127.98,80.36 ; 127.84,83.44 R513.1 R514.2
PMIC_GPIO_0: length 9.8
  TOP w0.127: R205.1 121.44,65.52 121.44,67.29 121.74,67.59 121.74,69.14 121.34,69.55 121.34,70.16 123.18,72.01 123.18,73.02 123.58,73.42 U45.B12
PMIC_GPIO_1: length 7
  TOP w0.203: U45.C13 122.78,74.22 121.87,73.31 121.87,71.33 v2(119.84,69.29) R191.1
PMIC_GPIO_2: length 7.1
  TOP w0.127: 122.5,65.99 122.5,70.69 123.58,71.77 U45.A12
PMIC_GPIO_3: length 1.3
  TOP w0.102: v1(125.58,78.62) U45.H9
  BOTTOM w0.127: R535.1 125.58,78 v1(125.58,78.62)
PMIC_GPIO_4_6: length 0.6
  TOP w0.102: U45.K10 v1(124.78,80.22)
PMIC_GPIO_5: length 1.3
  TOP w0.102: v1(124.78,73.82) U45.C10
  BOTTOM w0.254: v1(124.78,73.82) 125.43,73.82 R565.1
PMIC_GPIO_6_4: length 0.6
  TOP w0.102: v1(123.98,82.62) U45.N11
PMIC_GPIO_7: length 4
  TOP w0.102: v1(125.58,77.02) U45.G9
  BOTTOM w0.127: v1(125.58,77.02) U45.G9 126.83,77.42 127.04,77.62 R534.2 127.51,77.93 127.84,77.6 R537.1
PMIC_INT: length 0.5
  TOP w0.102: v1(60.71,56.47) U52.AC17
PMIC_PWRDOWN: length 2
  TOP w0.102: v1(127.18,80.22) U45.K8
  BOTTOM w0.127: R483.1 124.88,84.15 R516.2 125.68,84.15
PMIC_REGEN1: length 0.6
  TOP w0.102: v1(126.38,76.22) 126.78,76.62 U45.F8
PMIC_RESET_IN: length 1.6
  TOP w0.102: U45.K9 v1(125.58,80.22)
  BOTTOM w0.203: v1(125.58,80.22) 126.05,80.69 126.05,80.88 R533.2
PWRON: length 0.6
  TOP w0.102: U45.G8 126.78,77.42 v1(126.38,77.02)
RPWRON: length 1.4
  TOP w0.102: v1(123.98,73.82) U45.C11
  TOP w0.127: R194.2 v2(120.98,68.91)
RTC_PORZ: length 0.5
  TOP w0.102: v1(60.78,57.25) 61.13,56.85
SMPS_7: length 10.2
  TOP w0.127: 141.43,71.02 L18.1 ; L18.1 141.43,73.66 ; L18.1 140.42,72.34 ; L18.1 142.43,72.34
  BOTTOM w1.016: C409.2 142.09,74.04 ; C409.2 143.15,72.34 ; C409.2 141.02,72.34 ; C409.2 142.09,70.64
  vias: v2(143.59,74.12) v2(143.59,73.36) v2(143.59,72.6) v2(143.59,71.83) v2(143.59,71.07) v2(143.59,70.31) v2(144.35,74.12) v2(144.35,73.36) v2(144.35,72.6) v2(144.35,71.83) v2(144.35,71.07) v2(144.35,70.31)
SMPS_8: length 9
  TOP w1.016: L9.1 122,92.34 ; L9.1 122,90.18 ; L9.1 123.39,91.26 ; L9.1 120.6,91.26
  BOTTOM w0.635: 122,90.78 C328.2 ; C328.2 120.22,91.93 ; C328.2 122,93.07
SW1: length 5.8
  TOP w0.102: 122.78,75.47 U45.E13 ; U45.E13 122.43,75.82 ; U45.E13 123.14,75.82 ; U45.E12 123.94,75.82 ; U45.E12 123.23,75.82 ; U45.E12 123.58,75.47
  TOP w0.127: 117.81,71.02 L17.2 ; L17.2 117.81,73.66 ; L17.2 118.81,72.34
  vias: v1(121.49,75.77) v1(121.49,74.62) v1(122.38,75.42) v2(118.11,70.31) v2(118.95,73.87) v2(118.95,70.82)
SW2: length 5.8
  TOP w0.102: U45.F13 123.14,76.62 ; U45.F13 122.78,76.98 ; U45.F13 122.43,76.62 ; U45.F12 123.94,76.62 ; U45.F12 123.58,76.98 ; U45.F12 123.23,76.62
  TOP w0.127: 117.81,75.59 L15.2 ; L15.2 117.81,78.23 ; L15.2 118.81,76.91
  vias: v1(121.62,77.82) v1(122.12,76.74) v2(118.11,74.88) v2(118.69,78.69) v2(118.95,75.39) v2(120.47,77.85)
SW3: length 6.5
  TOP w0.102: U45.J13 122.78,79.38 ; U45.J13 122.43,79.02 ; U45.J13 123.14,79.02 ; 124.03,79.02 U45.J11 124.38,79.38 ; 123.23,79.02 U45.J12 ; U45.J12 123.58,79.38 ; U45.J12 123.94,79.02
  TOP w0.127: 117.81,80.16 L13.2 ; L13.2 117.81,82.81 ; L13.2 118.81,81.49
  vias: v1(122.38,79.42) v1(123.18,79.42) v2(118.11,83.52) v2(118.82,79.89) v2(118.95,83.01) v2(119.46,81.87) v2(119.96,82.76) v2(121.08,80.9) v2(121.11,79.58)
SW4: length 5.8
  TOP w0.102: 132.38,77.07 U45.G1 ; U45.G1 132.74,77.42 ; U45.G1 132.03,77.42 ; U45.G2 131.94,77.42 ; U45.G2 131.23,77.42 ; U45.G2 131.58,77.07
  TOP w0.305: L16.2 138.13,78.23 ; L16.2 137.12,76.91 ; L16.2 138.13,75.59
  vias: v1(133.05,77.17) v2(133.93,77.29) v2(133.93,76.28) v2(136.47,76.79) v2(136.98,78.44) v2(136.98,75.39)
SW5: length 5.8
  TOP w0.102: U45.H1 132.74,78.22 ; U45.H1 132.38,78.58 ; U45.H1 132.03,78.22 ; 131.23,78.22 U45.H2 ; U45.H2 131.94,78.22 ; U45.H2 131.58,78.58
  TOP w0.305: L14.2 138.13,82.81 ; L14.2 137.12,81.49 ; L14.2 138.13,80.16
  vias: v1(131.98,78.62) v1(133.05,78.62) v2(133.93,78.62) v2(135.08,79.07) v2(135.97,82.37) v2(136.09,81.23) v2(136.22,83.64) v2(136.98,83.01) v2(136.98,79.96) v2(137.82,83.52)
SW6: length 5.4
  TOP w0.102: 129.18,81.87 U45.N5 ; U45.N5 129.54,82.22 ; U45.N5 129.18,82.58 ; 129.54,81.42 U45.M5 129.18,81.78
  TOP w0.305: 129.82,87.96 L11.2 ; L11.2 131.14,86.96 ; L11.2 132.46,87.96
  vias: v1(129.74,83.52) v2(129.62,86.82) v2(130.76,84.28) v2(132.16,85.55) v2(132.66,86.82) v2(133.17,87.66)
SW7: length 6.5
  TOP w0.102: 131.58,74.67 U45.D2 ; U45.D2 131.23,75.02 ; U45.D2 131.94,75.02 ; 132.03,75.02 U45.D1 ; U45.D1 132.38,74.67 ; U45.D1 132.74,75.02 ; 130.78,74.67 U45.D3 131.14,75.02
  TOP w0.305: 138.13,71.02 L18.2 ; L18.2 138.13,73.66 ; L18.2 137.12,72.34
  vias: v1(131.19,74.62) v1(131.99,74.62) v1(132.78,74.62) v2(135.84,73.36) v2(136.22,72.21) v2(136.98,73.87)
SW8: length 4.7
  TOP w0.102: 125.18,81.87 U45.N10 ; U45.N10 124.83,82.22 ; U45.N10 125.18,82.58
  TOP w0.305: L9.2 123.32,87.96 ; L9.2 120.67,87.96 ; L9.2 122,86.96
  vias: v1(123.39,83.77) v2(120.47,86.82) v2(122.12,86.06) v2(122.12,85.17) v2(122.76,86.64) v2(122.89,85.55) v2(123.52,84.79)
SW9: length 5.1
  TOP w0.102: 127.58,81.87 U45.N7 ; U45.N7 127.94,82.22 ; U45.N7 127.58,82.58 ; U45.N7 127.23,82.22
  TOP w0.305: 126.57,86.96 L10.2 ; L10.2 127.89,87.96 ; L10.2 125.25,87.96
  vias: v1(127.98,82.62) v1(127.98,81.82) v2(127.08,86.65) v2(127.84,85.8) v2(128.09,86.82)
VCAP_VBBLDO_DSPEVE: length 7.5
  TOP w0.178: v1(70.36,62.84) U52.K9
  BOTTOM w0.127: 69.94,64.62 69.95,64.19
  BOTTOM w0.152: 69.93,64.73 69.94,64.62
  BOTTOM w0.178: 69.91,65.49 69.91,65.12
  BOTTOM w0.203: 69.91,65.12 69.93,65.05
  BOTTOM w0.254: 69.98,67.13 69.9,66.88 69.94,66.32 69.94,66.27 69.92,66.05 69.91,65.49 ; 69.95,64.19 70.21,63.17 v1(70.36,62.84) ; 69.93,65.05 69.93,64.73
  BOTTOM w0.305: 70,68.79 70,67.34 69.98,67.13
  BOTTOM w0.381: C477.1 70,68.79
VCAP_VBBLDO_GPU: length 5.3
  TOP w0.178: v1(62.34,59.64) U52.Y14
  BOTTOM w0.127: 60.48,60.06 60.87,60.06 60.89,60.07 ; 61.32,60.07 61.36,60.07 61.37,60.06 61.54,60.06 61.8,60.07 ; 59.72,60.07 59.77,60.05 59.77,60.05 60.1,60.05
  BOTTOM w0.152: 59.51,60.25 59.51,60.81
  BOTTOM w0.178: 61.32,60.07 60.89,60.07 ; 60.48,60.06 60.1,60.05
  BOTTOM w0.203: 59.72,60.07 59.51,60.25
  BOTTOM w0.254: v1(62.34,59.64) 61.8,60.07
  BOTTOM w0.381: C501.1 59.13,61.29 59.51,60.81
VCAP_VBBLDO_IVA: length 15.4
  TOP w0.381: U52.R20 v1(67.11,54.03)
  L6-SIGNAL w0.127: 60.35,53.62 60.15,53.6 59.78,53.6 59.78,53.59 59.74,53.59 ; 65.24,54.45 65.56,54.45 65.96,54.46 ; 58.9,53.65 58.98,53.65 58.99,53.63 59.25,53.63 59.27,53.61 59.35,53.61 ; 64.44,53.66 62.76,53.66
  L6-SIGNAL w0.152: 59.74,53.59 59.72,53.61
  L6-SIGNAL w0.203: 59.72,53.61 59.35,53.61 ; 58.9,53.65 58.57,53.81
  L6-SIGNAL w0.254: 62.76,53.66 62.56,53.47
  L6-SIGNAL w0.305: 65.24,54.45 64.44,53.66
  L6-SIGNAL w0.381: v1(67.11,54.03) 66.47,54.6 65.96,54.46 ; 60.35,53.62 60.37,53.64 60.52,53.79 60.63,53.79 60.78,53.85 ; 62.56,53.47 61.34,53.47 60.97,53.85
  L6-SIGNAL w0.508: v1(54.58,54.51) 54.81,54.51 55.42,53.9 55.82,53.89 57.77,53.89 57.85,53.81 58.57,53.81 ; 60.97,53.85 60.78,53.85
  BOTTOM w0.508: v1(54.58,54.51) 54.25,54.18 C519.1
VCAP_VBBLDO_MPU: length 9.9
  TOP w0.178: U52.J16 v1(71.14,57.21)
  BOTTOM w0.127: 73.33,56.85 73.33,56.85 73.34,56.85 73.74,56.85 73.74,56.85 73.89,56.85 ; 71.75,56.82 72.19,56.82 ; 72.98,56.85 72.76,56.84 72.56,56.84 72.5,56.83
  BOTTOM w0.152: 74.75,56.72 74.75,56.14 ; 74.79,55.81 74.79,55.47 ; 74.51,56.87 74.49,56.85 74.19,56.85
  BOTTOM w0.178: 75.28,55.24 75.26,55.24 75.26,55.24 75.02,55.24 74.79,55.47
  BOTTOM w0.203: 75.45,54.54 75.54,54.63 75.54,55.01 75.32,55.24 75.28,55.24 ; 73.89,56.85 74.19,56.85 ; 72.19,56.82 72.5,56.83 ; 74.79,55.81 74.78,55.82 74.78,55.86 74.75,55.89 74.75,56.14 ; 71.53,56.97 71.75,56.82 ; 74.51,56.87 74.75,56.72 ; 72.98,56.85 73.33,56.85
  BOTTOM w0.254: 75.45,54.54 75.45,54.49 75.53,54.41 ; v1(71.14,57.21) 71.53,56.97
  BOTTOM w0.356: 75.9,54.41 76.68,54.4 76.92,54.39 77.04,54.38
  BOTTOM w0.381: 75.9,54.41 75.89,54.41 75.53,54.41 ; 77.04,54.38 77.37,53.98
  BOTTOM w0.508: 77.37,53.98 C509.1
VCAP_VDDRAM_CORE1: length 8.9
  TOP w0.178: v1(69.54,62.89) U52.L9
  BOTTOM w0.127: 67.53,64.72 67.51,64.29
  BOTTOM w0.152: 67.51,64.29 67.51,64.34 67.54,64.19 ; 67.54,63.9 67.54,63.83 67.54,63.67 67.54,63.4 ; 68.5,63.25 69.06,63.25
  BOTTOM w0.178: 67.54,65.59 67.51,65.33 67.51,64.95
  BOTTOM w0.254: 69.06,63.25 v1(69.54,62.89) ; 67.54,63.4 67.78,63.2 68.16,63.2 68.25,63.25 68.5,63.25 ; 67.54,65.59 67.52,65.86 67.52,66.09 67.55,66.27 67.55,66.6 67.49,66.86 67.53,67.05 67.61,67.14 67.61,67.49 67.57,67.54 67.57,67.97 ; 67.54,64.19 67.54,63.9 ; 67.51,64.95 67.53,64.72
  BOTTOM w0.305: 67.57,67.97 67.61,67.97 67.61,68.61
  BOTTOM w0.381: C468.1 67.7,68.7 67.61,68.61
VCAP_VDDRAM_CORE2: length 12
  TOP w0.178: U52.J19 v1(71.94,54.85)
  L3-SIGNAL w0.127: 74.03,53.64 73.99,53.67
  L3-SIGNAL w0.152: 72.59,54.41 72.56,54.41 72.47,54.49 72.21,54.74
  L3-SIGNAL w0.178: 74.68,53.65 74.03,53.64
  L3-SIGNAL w0.203: 72.97,54.31 72.87,54.41 72.59,54.41
  L3-SIGNAL w0.254: v1(71.94,54.85) 71.95,54.84 72.11,54.74 72.21,54.74
  L3-SIGNAL w0.381: v1(79.32,50.34) 79.32,51.13 79.3,51.16 79.3,52 78.91,52.39 78.22,52.39 77.01,53.59 76.76,53.59 76.66,53.69 75.38,53.69 75.35,53.72 74.92,53.72 74.68,53.65 ; 73.99,53.67 73.33,54.31 72.97,54.31
  BOTTOM w0.305: v1(79.32,50.34) 79.32,50.57
  BOTTOM w0.381: C517.1 79.43,50.68 79.32,50.57
VCAP_VDDRAM_CORE3: length 4.6
  TOP w0.178: v1(62.33,58.06) U52.Y15
  BOTTOM w0.178: 60.09,58.56 60.15,58.5 ; 61.36,58.5 61.88,58.5 61.9,58.52
  BOTTOM w0.203: 61.9,58.52 61.96,58.47 61.99,58.47 ; 61.36,58.5 61.34,58.48 60.56,58.48 60.15,58.5
  BOTTOM w0.381: 59.69,58.88 60.09,58.56 ; 61.99,58.47 v1(62.33,58.06)
  BOTTOM w0.508: C506.1 59.69,58.88
VCAP_VDDRAM_CORE4: length 17.2
  TOP w0.178: v1(67.13,55.68) U52.P19
  L3-SIGNAL w0.127: 73.94,52.62 73.94,52.61 73.94,52.6 73.94,52.2 73.94,52.2 73.94,52.05 ; 71.77,54.45 71.77,54.45 71.73,54.45 ; 71.29,54.45 70.95,54.45 ; 69.82,54.46 69.33,54.45 ; 73.4,52.85 73.37,52.85
  L3-SIGNAL w0.152: 72.55,54.01 72.12,54.44 72.03,54.44 72.02,54.45 71.77,54.45 ; 73.17,53.53 73.17,53.08 73.2,53.05 73.2,53.01 73.37,52.85 ; 72.95,53.76 72.87,53.76 ; 73.4,52.85 73.41,52.84 73.72,52.84 73.94,52.62
  L3-SIGNAL w0.178: 71.73,54.45 71.29,54.45 ; 70.95,54.45 70.69,54.46
  L3-SIGNAL w0.203: 69.33,54.45 68.94,54.45 68.58,54.45 68.57,54.46 68.4,54.46 ; 72.61,54.01 72.55,54.01
  L3-SIGNAL w0.254: 78.8,50.31 78.79,50.3 78.79,49.72
  L3-SIGNAL w0.305: 72.87,53.76 72.61,54.01 ; 70.69,54.46 69.82,54.46 ; 73.17,53.53 72.95,53.76
  L3-SIGNAL w0.381: 76.86,51.67 77.7,50.6 77.74,50.56 78.55,50.56 78.8,50.31 ; 78.79,49.72 78.79,49.35 v1(78.69,49.25) ; 74.55,51.67 74.22,51.67 73.94,52.05 ; 68.4,54.46 v1(67.13,55.68)
  L3-SIGNAL w0.508: 76.86,51.67 74.55,51.67
  BOTTOM w0.254: 78.74,49.3 v1(78.69,49.25)
  BOTTOM w0.381: C516.1 78.74,49.3
VCAP_VDDRAM_CORE5: length 8.5
  TOP w0.178: U52.Y16 v1(62.38,57.27)
  BOTTOM w0.102: C512.1 55.85,58.7
  BOTTOM w0.127: 61.04,57.66 60.75,57.66 60.57,57.66 60.56,57.66 60.5,57.66 ; 60.12,57.66 60.11,57.65 59.78,57.65 ; 58.83,57.64 59.15,57.64 59.35,57.65 ; 59.74,57.65 59.74,57.65
  BOTTOM w0.178: 60.12,57.66 60.5,57.66 ; 59.74,57.65 59.78,57.65 ; 59.35,57.65 59.74,57.65
  BOTTOM w0.254: 61.04,57.66 61.27,57.55
  BOTTOM w0.305: 58.42,57.15 58.83,57.64
  BOTTOM w0.381: v1(62.38,57.27) 61.72,57.27 61.27,57.55
  BOTTOM w0.508: 55.85,58.7 56.57,57.15 58.42,57.15
VCAP_VDDRAM_DSPEVE1: length 7.9
  TOP w0.178: v1(71.12,62.85) U52.J10
  BOTTOM w0.127: 70.76,64.21 70.76,64.72 ; 70.91,64.85 71.4,64.87
  BOTTOM w0.254: 70.76,64.21 70.76,63.95 70.66,63.84 70.66,63.43 v1(71.12,62.85) ; 71.4,64.87 71.77,65.18 ; 70.91,64.85 70.87,64.82 70.76,64.72
  BOTTOM w0.508: 71.77,65.18 C481.1
VCAP_VDDRAM_DSPEVE2: length 7.1
  TOP w0.178: U52.J9 v1(71.12,63.65)
  BOTTOM w0.127: 73.13,64.59 73.13,64.26 73.36,64.05 73.68,64.05 ; 74.15,64.07 74.26,64.07 74.48,64.07 74.48,64.06 74.5,64.06
  BOTTOM w0.152: 73.68,64.05 74.15,64.07 ; 72.34,64.87 72.95,64.87 73.13,64.59 ; 74.5,64.06 74.68,64.06
  BOTTOM w0.178: 71.7,64.26 71.71,64.29
  BOTTOM w0.203: v1(71.12,63.65) 71.27,63.86 71.7,64.26
  BOTTOM w0.381: 74.68,64.06 75.16,63.58 ; 71.71,64.29 72.34,64.87
  BOTTOM w0.508: 75.16,63.58 C462.1
VCAP_VDDRAM_GPU: length 10.1
  TOP w0.102: U52.Y13 v1(62.33,60.45)
  L3-SIGNAL w0.127: 60.16,60.87 59.74,60.86
  L3-SIGNAL w0.203: 59.74,60.86 59.21,61.32 ; 60.5,61.04 60.16,60.87
  L3-SIGNAL w0.381: v1(62.33,60.45) 61.77,61.04
  L3-SIGNAL w0.508: v1(54.4,61) 54.64,61.01 54.89,61.32 59.21,61.32 ; 60.5,61.04 60.92,61.04 61.29,61.04 61.77,61.04
  BOTTOM w0.381: v1(54.4,61) 54.44,61.04 54.48,61.04 54.64,61.19 54.79,61.19 C480.1
VCAP_VDDRAM_IVA: length 17.4
  TOP w0.178: U52.T20 v1(65.54,54.03)
  L6-SIGNAL w0.127: 62.74,52.86 64.1,52.86 64.1,52.86 64.41,52.86
  L6-SIGNAL w0.305: 64.41,52.86 v1(65.54,54.03)
  L6-SIGNAL w0.381: 62.33,52.43 62.74,52.86
  L6-SIGNAL w0.762: 62.33,52.43 62.33,49.13 60.53,47.32 v2(54.41,47.32)
  BOTTOM w0.305: C529.1 55.1,46.63 v2(54.41,47.32)
VCAP_VDDRAM_MPU1: length 7.1
  TOP w0.178: U52.K16 v1(71.15,58.04)
  BOTTOM w0.127: 72.26,57.66 72.22,57.65 71.98,57.65 71.67,57.71
  BOTTOM w0.152: 73.44,58.48 73.15,58.24 73.15,57.86 73.05,57.76 73.04,57.76 72.91,57.64 72.58,57.64 72.55,57.66 72.26,57.66
  BOTTOM w0.178: 73.59,58.48 73.44,58.48
  BOTTOM w0.203: 74.02,58.75 73.59,58.48
  BOTTOM w0.254: 71.67,57.71 v1(71.15,58.04)
  BOTTOM w0.508: C504.1 74.02,58.75
VCAP_VDDRAM_MPU2: length 10.5
  TOP w0.178: U52.K19 v1(71.12,54.86)
  L3-SIGNAL w0.178: 75.34,55.21 74.95,55.28 ; 74.12,55.22 74.18,55.22 74.19,55.21 74.38,55.21 74.6,55.22
  L3-SIGNAL w0.203: 73.79,55.27 73.23,55.27
  L3-SIGNAL w0.254: 75.34,55.21 75.39,55.21 75.95,54.36 ; 73.79,55.27 74.07,55.27 74.12,55.22 ; 74.95,55.28 74.6,55.22 ; 73.23,55.27 73.05,55.4
  L3-SIGNAL w0.381: v1(78.69,53.19) 78.1,53.19 77.21,54.08 77.17,54.08 76.89,54.36 75.95,54.36 ; 73.05,55.4 71.53,55.4 v1(71.12,54.86)
  BOTTOM w0.381: C520.1 v1(78.69,53.19)
VEVM_3V3: length 48.2
  TOP w0.203: U45.J1 132.38,79.02 v1(132.78,79.42) ; v1(131.98,79.42) 131.58,79.02 U45.J2 U45.J3
  TOP w0.254: U45.L12 123.58,80.62 v1(123.18,81.02) ; v1(123.18,77.82) U45.G12 ; v1(122.38,77.82) U45.G13 ; v1(128.78,81.82) U45.M6 ; U45.M9 v1(126.38,81.82) U45.M8 ; v1(131.19,76.22) U45.F3 ; v1(126.38,82.62) U45.N8 ; v1(122.38,81.02) 122.78,80.62 U45.L13 ; U45.H11 v1(123.98,77.82) U45.G11 ; v1(131.99,75.42) 131.58,75.82 U45.E2 ; U45.C4 v1(129.58,73.82) 129.18,74.22 U45.C5 ; v1(123.98,74.62) U45.D11 ; v1(132.78,75.42) 132.38,75.82 U45.E1 ; U45.F1 132.38,76.62 v1(132.78,76.22) ; U45.F2 131.58,76.62 v1(131.99,76.22) ; v1(122.38,78.62) U45.H13 ; v1(128.78,82.62) U45.N6 ; v1(123.18,74.62) U45.D12 ; v1(131.19,75.42) U45.E3 ; v1(122.38,74.62) 122.78,75.02 U45.D13 ; R194.1 v2(120.98,66.63) ; v1(123.18,78.62) U45.H12 ; v1(125.58,82.62) U45.N9
  TOP w0.381: R193.1 v2(126.7,67.01)
  BOTTOM w0.254: C338.2 129.29,84.66 128.78,84.16 v1(128.78,82.62) ; R549.1 131.99,71.77 132.34,71.42 v1(132.78,71.42) ; C342.2 122.58,83.75 123.14,83.19 124.16,83.19 124.72,82.62 v1(125.58,82.62) 125.58,83.11 125.26,83.43 R516.1 ; C346.2 v1(122.38,81.02) ; v1(122.38,74.62) 121.77,75.24 C379.2 ; C375.2 134.8,76.2 134.19,76.81 133.5,76.81 133.4,76.71 132.47,76.71 v1(131.99,76.22) ; v1(126.38,82.62) 126.38,83.26 126.19,83.46 126.19,84.53 125.63,85.09 C341.2 ; C380.2 133.73,74.88 133.32,74.88 v1(132.78,75.42) ; v1(123.18,77.82) 122.63,77.27 121.13,77.27 C376.2 ; v1(126.38,78.62) 126.38,77.96 R534.1 ; v1(122.38,78.62) 121.28,78.62 120.78,79.12 C354.2 ; v1(131.98,79.42) 132.52,79.96 133.99,79.96 C353.2
